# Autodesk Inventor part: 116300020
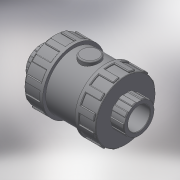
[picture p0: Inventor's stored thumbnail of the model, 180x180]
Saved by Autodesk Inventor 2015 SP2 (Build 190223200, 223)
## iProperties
Created: 2017-11
Part Number: 116300020
Material: Generic
Description: PLASSON AIR RELEASE VALVE CEM PVC 20
Document SubType Name: Modeling
Designer: KIM
Density: 1 g/cm^3
Appearance: Default
Author: KIM
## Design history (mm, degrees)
derived "116300 - 116900.ipt"
feature "Solid1::116300 - 116900.ipt"
tag "TaggingFeature1"
body "Solid1"
other parameters: "d0" = 75, "d2" = 45, "d3" = 16, "d4" = 16, "d5" = 11.2, "d7" = 28, "d8" = 40.5, "d13" = 0.6, "d23" = 16, "d24" = 43.2, "d25" = 0.4, "d26" = 0.6, "d27" = 6.75, "d28" = 3.375, "d29" = 12, "d30" = 0, "d35" = 0.6, "d39" = 22.5, "d45" = 360 deg, "d47" = 0.4, "d50" = 22.5, "d51" = 13.5, "d53" = 0, "d54" = 0.9, "d55" = 4, "d56" = 2, "d58" = 0, "d59" = 0.6, "d61" = 360 deg, "l_" = 16, "H_" = 75, "K_" = 45
